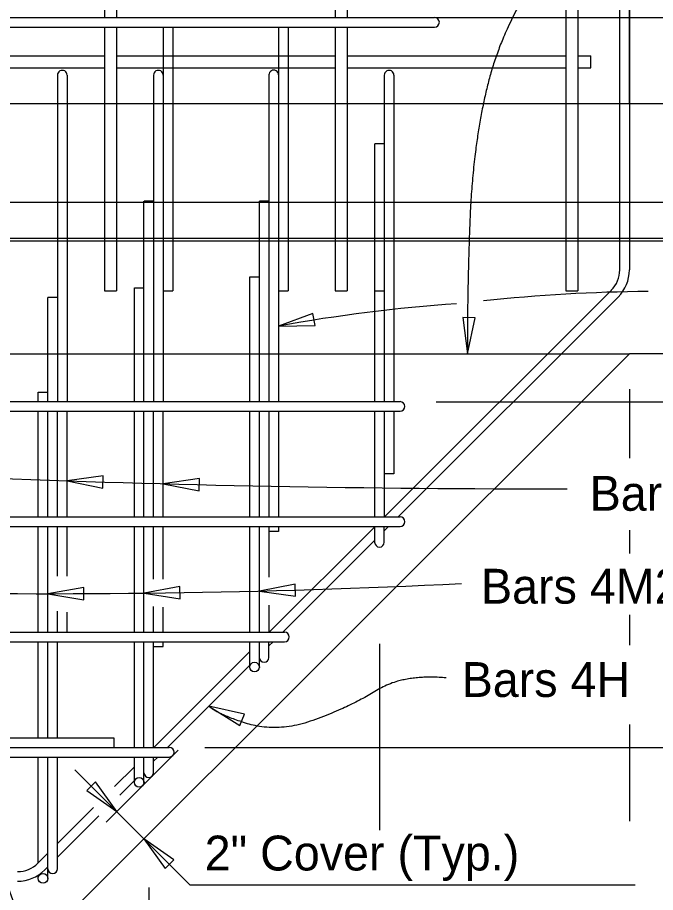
# Model space of a CAD drawing. Extents: x 0 to 54.1, y -0.5 to 22.5.
# Drawn here: x 9.017 to 11.782, y 5.878 to 9.674 of the extents above; entities that cross this region are included whole.
import ezdxf

# ---------------------------------------------------------------- set-up
doc = ezdxf.new("R2010")
doc.units = 0
for name, color, linetype in [('Dimension', 7, 'Continuous'), ('ElectricalConduit', 7, 'Continuous'), ('Rebar', 7, 'Continuous'), ('TextStructures', 7, 'Continuous'), ('WallConc', 7, 'Continuous'), ('WallConc_h', 7, 'Continuous')]:
    doc.layers.add(name, color=color, linetype=linetype)

msp = doc.modelspace()

# ---------------------------------------------------------------- linework, layer by layer
at = {"layer": 'Dimension'}
for p, q in [((10.8285, 9.6745), (15.0161, 9.6745)), ((11.6693, 8.0627), (11.6693, 7.7621)), ((10.8322, 8.0076), (15.0161, 8.0076)), ((11.6693, 7.4503), (11.6693, 7.3494)), ((11.6693, 7.0828), (11.6693, 6.952)), ((10.586, 6.9569), (10.586, 6.1481)), ((11.6693, 6.6066), (11.6693, 6.1883)), ((9.7133, 6.4957), (9.4012, 6.1837)), ((9.8294, 6.5076), (15.0161, 6.5076)), ((9.2655, 6.4109), (9.7643, 5.9121)), ((9.586, 5.9004), (9.586, 5.5429)), ((9.7643, 5.9121), (11.6935, 5.9121))]:
    msp.add_line(p, q, dxfattribs=at)
for points in [[(10.1484, 8.3359), (10.3068, 8.3375), (10.2974, 8.3896)], [(10.9679, 8.216), (11, 8.3712), (10.9471, 8.3731)], [(9.2317, 7.6641), (9.3869, 7.6325), (9.3887, 7.6854)], [(9.6484, 7.6517), (9.8038, 7.6211), (9.8052, 7.674)], [(10.0651, 7.1863), (10.2219, 7.1638), (10.2205, 7.2167)], [(9.1483, 7.1746), (9.3045, 7.1482), (9.3045, 7.2011)], [(9.5651, 7.1771), (9.7215, 7.1524), (9.7209, 7.2054)], [(9.846, 6.6874), (9.9799, 6.6027), (10.0003, 6.6515)], [(9.447, 6.2294), (9.3552, 6.3586), (9.3178, 6.3212)], [(9.5648, 6.1116), (9.6566, 5.9824), (9.694, 6.0198)]]:
    msp.add_lwpolyline(points, close=True, dxfattribs=at)
for centre, radius, start, end in [((11.8036, 1.3075), 7.1784, 90.42454, 96.13586), ((11.4249, 1.272), 7.1783, 94.0349, 100.24317), ((11.3262, 71.0554), 63.4258, 265.430565, 270.066093), ((9.137, 43.8447), 36.6701, 264.80234, 272.81919)]:
    msp.add_arc(centre, radius, start, end, dxfattribs=at)
msp.add_ellipse((9.2934, 6.7682), major_axis=(-0.0432, 1.3047), ratio=0.351657, start_param=1.406981, end_param=3.141593, dxfattribs=at)
for points in [[(12.3277, 10.509), (12.0001, 10.5136), (11.5221, 10.2266), (11.1233, 9.6574), (10.9889, 9.1194), (10.9645, 8.4224), (10.9679, 8.216)], [(10.8746, 6.8093), (10.6884, 6.8264), (10.4579, 6.6832), (10.1441, 6.5695), (9.8774, 6.6536), (9.846, 6.6874)]]:
    msp.add_open_spline(points, degree=2, dxfattribs=at)
at = {"layer": 'ElectricalConduit'}
for p, q in [((13.8673, 8.8714), (3.669, 8.8714)), ((13.8673, 8.7047), (3.669, 8.7047))]:
    msp.add_line(p, q, dxfattribs=at)
at = {"layer": 'Rebar'}
for p, q in [((9.3932, 14.4888), (9.3932, 9.6745)), ((9.4453, 14.4888), (9.4453, 9.6745)), ((10.3932, 14.4888), (10.3932, 9.6745)), ((10.4453, 14.4888), (10.4453, 9.6745)), ((11.3932, 14.4888), (11.3932, 8.4888)), ((11.4453, 14.4888), (11.4453, 8.4888)), ((11.6274, 8.5795), (11.6274, 10.5105)), ((11.6691, 10.5105), (11.6691, 8.5795)), ((5.013, 9.6745), (10.8245, 9.6745)), ((7.0121, 9.6328), (10.8245, 9.6328)), ((9.3932, 9.6328), (9.3932, 8.4888)), ((9.4453, 9.6328), (9.4453, 8.4888)), ((9.6484, 9.6328), (9.6484, 8.4888)), ((9.6901, 9.6328), (9.6901, 8.4888)), ((10.1484, 9.6328), (10.1484, 8.4888)), ((10.1901, 9.6328), (10.1901, 8.4888)), ((10.3932, 9.6328), (10.3932, 8.4888)), ((10.4453, 9.6328), (10.4453, 8.4888)), ((8.4453, 9.5077), (9.3932, 9.5077)), ((9.4453, 9.5077), (10.3932, 9.5077)), ((10.4453, 9.5077), (11.3932, 9.5077)), ((11.4453, 9.5077), (11.5024, 9.5077)), ((11.5024, 9.4556), (11.5024, 9.5077)), ((8.4453, 9.4556), (9.3932, 9.4556)), ((9.4453, 9.4556), (10.3932, 9.4556)), ((10.4453, 9.4556), (11.3932, 9.4556)), ((11.4453, 9.4556), (11.5024, 9.4556)), ((9.19, 9.4243), (9.19, 8.0078)), ((9.2317, 9.4243), (9.2317, 8.0078)), ((9.6067, 9.4243), (9.6067, 8.0078)), ((9.6484, 9.4243), (9.6484, 8.0078)), ((10.1067, 9.4253), (10.1067, 8.0078)), ((10.1484, 9.4253), (10.1484, 8.0078)), ((10.6067, 9.4243), (10.6067, 8.0078)), ((10.6484, 9.4243), (10.6484, 8.0078)), ((10.6067, 9.127), (10.565, 9.127)), ((10.565, 8.0078), (10.565, 9.127)), ((9.565, 8.0078), (9.565, 8.877)), ((9.6067, 8.877), (9.5651, 8.877)), ((10.065, 8.0078), (10.065, 8.877)), ((10.1067, 8.877), (10.0651, 8.877)), ((10.0233, 8.5495), (10.0651, 8.5495)), ((10.0233, 8.0078), (10.0233, 8.5495)), ((9.3932, 8.4888), (9.4453, 8.4888)), ((9.5233, 8.5021), (9.5651, 8.5021)), ((9.5233, 8.0078), (9.5233, 8.5021)), ((9.6484, 8.4888), (9.6901, 8.4888)), ((10.1484, 8.4888), (10.1901, 8.4888)), ((10.3932, 8.4888), (10.4453, 8.4888)), ((10.565, 8.4888), (10.6067, 8.4888)), ((10.6075, 7.5078), (11.5908, 8.4912)), ((11.3932, 8.4888), (11.4453, 8.4888)), ((9.19, 8.4603), (9.1483, 8.4603)), ((9.1483, 8.0078), (9.1483, 8.4603)), ((11.6203, 8.4617), (10.6664, 7.5078)), ((9.1066, 8.0078), (9.1066, 8.0483)), ((9.1067, 8.0483), (9.1484, 8.0483)), ((5.1215, 8.0078), (10.6748, 8.0078)), ((6.8623, 7.9661), (10.6748, 7.9661)), ((9.1066, 7.5078), (9.1066, 7.9661)), ((9.1483, 7.5078), (9.1483, 7.9661)), ((9.19, 7.5078), (9.19, 7.9661)), ((9.2317, 7.5078), (9.2317, 7.9661)), ((9.5233, 7.5078), (9.5233, 7.9661)), ((9.565, 7.5078), (9.565, 7.9661)), ((9.6067, 7.5078), (9.6067, 7.9661)), ((9.6484, 7.5078), (9.6484, 7.9661)), ((10.0233, 7.5078), (10.0233, 7.9661)), ((10.065, 7.5078), (10.065, 7.9661)), ((10.1067, 7.9661), (10.1067, 7.5078)), ((10.1484, 7.9661), (10.1484, 7.5078)), ((10.565, 7.5078), (10.565, 7.9661)), ((10.6067, 7.9661), (10.6067, 7.5078)), ((10.6484, 7.9661), (10.6484, 7.6952)), ((10.6484, 7.6952), (10.6067, 7.6952)), ((5.1215, 7.5078), (10.6748, 7.5078)), ((6.8623, 7.4661), (10.6748, 7.4661)), ((9.1066, 7.0078), (9.1066, 7.4661)), ((9.1483, 7.0078), (9.1483, 7.4661)), ((9.19, 7.2514), (9.19, 7.4661)), ((9.2317, 7.2514), (9.2317, 7.4661)), ((9.5233, 7.0078), (9.5233, 7.4661)), ((9.565, 7.0078), (9.565, 7.4661)), ((9.6067, 7.2379), (9.6067, 7.4661)), ((9.6484, 7.2379), (9.6484, 7.4661)), ((10.0233, 7.0078), (10.0233, 7.4661)), ((10.065, 7.0078), (10.065, 7.4661)), ((10.1067, 7.4661), (10.1067, 7.2463)), ((10.1484, 7.4452), (10.1067, 7.4452)), ((10.1074, 7.0078), (10.565, 7.4654)), ((10.1484, 7.4661), (10.1484, 7.4452)), ((10.565, 7.3979), (10.565, 7.4661)), ((10.6067, 7.3979), (10.6067, 7.4661)), ((10.6247, 7.4661), (10.6067, 7.4481)), ((10.565, 7.4064), (10.1664, 7.0078)), ((9.19, 7.0078), (9.19, 7.0991)), ((9.6067, 7.0078), (9.6067, 7.1194)), ((9.6484, 7.0078), (9.6484, 7.116)), ((10.1067, 7.1245), (10.1067, 7.0078)), ((9.2317, 7.0078), (9.2317, 7.0941)), ((5.6218, 7.0078), (10.174, 7.0078)), ((6.8615, 6.966), (10.174, 6.966)), ((9.1066, 6.5495), (9.1066, 6.966)), ((9.1483, 6.5495), (9.1483, 6.966)), ((9.19, 6.5495), (9.19, 6.966)), ((9.5233, 6.5078), (9.5233, 6.966)), ((9.565, 6.5078), (9.565, 6.966)), ((9.6067, 6.5078), (9.6067, 6.966)), ((9.6484, 6.9452), (9.6484, 6.966)), ((10.0233, 6.8562), (10.0233, 6.966)), ((10.065, 6.8551), (10.065, 6.966)), ((10.1067, 6.8979), (10.1067, 6.966)), ((10.1247, 6.966), (10.1067, 6.9481)), ((9.6067, 6.9452), (9.6484, 6.9452)), ((9.6074, 6.5078), (10.0233, 6.9237)), ((10.0233, 6.8647), (9.6664, 6.5078)), ((6.1209, 6.5495), (9.4342, 6.5495)), ((9.4342, 6.5495), (9.4342, 6.5078)), ((6.1218, 6.5078), (9.6748, 6.5078)), ((6.3623, 6.466), (9.6748, 6.466)), ((9.1066, 6.007), (9.1066, 6.466)), ((9.1483, 5.9395), (9.1483, 6.466)), ((9.19, 5.9812), (9.19, 6.466)), ((9.5233, 6.3562), (9.5233, 6.466)), ((9.565, 6.3562), (9.565, 6.466)), ((9.6247, 6.466), (9.6067, 6.4481)), ((9.6067, 6.3979), (9.6067, 6.466)), ((9.4373, 6.3377), (9.5233, 6.4237)), ((9.5233, 6.3647), (9.4598, 6.3012)), ((9.19, 6.0904), (9.3465, 6.2469)), ((9.3696, 6.211), (9.19, 6.0314)), ((9.1052, 6.0055), (9.1483, 6.0487)), ((9.1483, 5.9897), (9.1346, 5.976)), ((9.1066, 5.9395), (9.1066, 5.9535))]:
    msp.add_line(p, q, dxfattribs=at)
for centre in [(10.0442, 6.8562), (9.5442, 6.3562), (9.1275, 5.9395)]:
    msp.add_circle(centre, 0.0209, dxfattribs=at)
for centre, radius, start, end in [((10.8245, 9.6536), 0.0209, 270, 90), ((9.2108, 9.4243), 0.0209, 359.9399, 180), ((9.6275, 9.4243), 0.0209, 359.9399, 180), ((10.1275, 9.4253), 0.0209, 359.9399, 180), ((10.6275, 9.4243), 0.0209, 359.9399, 180), ((11.5024, 8.5795), 0.125, 315, 360), ((11.5024, 8.5795), 0.1667, 315, 360), ((10.6748, 7.987), 0.0209, 270, 90), ((10.6748, 7.487), 0.0209, 270, 90), ((10.5858, 7.3979), 0.0209, 180.0013, 0), ((10.174, 6.9869), 0.0209, 270, 90), ((10.0858, 6.8979), 0.0209, 180.0013, 0), ((9.6748, 6.4869), 0.0209, 270, 90), ((9.5858, 6.3979), 0.0209, 180.0013, 0), ((9.0168, 6.0939), 0.125, 270, 315), ((9.0168, 6.0939), 0.1667, 270, 315), ((9.1691, 5.9812), 0.0209, 180.0013, 0)]:
    msp.add_arc(centre, radius, start, end, dxfattribs=at)
at = {"layer": 'WallConc'}
for p, q in [((11.6693, 8.216), (9.1693, 5.7161)), ((13.8673, 8.216), (11.6693, 8.216))]:
    msp.add_line(p, q, dxfattribs=at)
at = {"layer": 'WallConc_h'}
for p, q in [((11.6693, 9.2995), (11.6693, 14.7577)), ((13.8673, 9.2995), (1.971, 9.2995)), ((13.8673, 8.7162), (1.971, 8.7162)), ((4.1692, 8.216), (11.6693, 8.216))]:
    msp.add_line(p, q, dxfattribs=at)

# ---------------------------------------------------------------- texts
at = {"layer": 'TextStructures'}
for s, p in [('Bars 4G1 (pairs)', (11.4969, 7.5346)), ('Bars 4M2 (See Note 7)', (11.0258, 7.1314)), ('Bars 4H', (10.9421, 6.7266)), ('2" Cover (Typ.)', (9.828, 5.9738))]:
    msp.add_text(s, height=0.1512, dxfattribs=at).set_placement(p)

doc.saveas('drawing.dxf')
